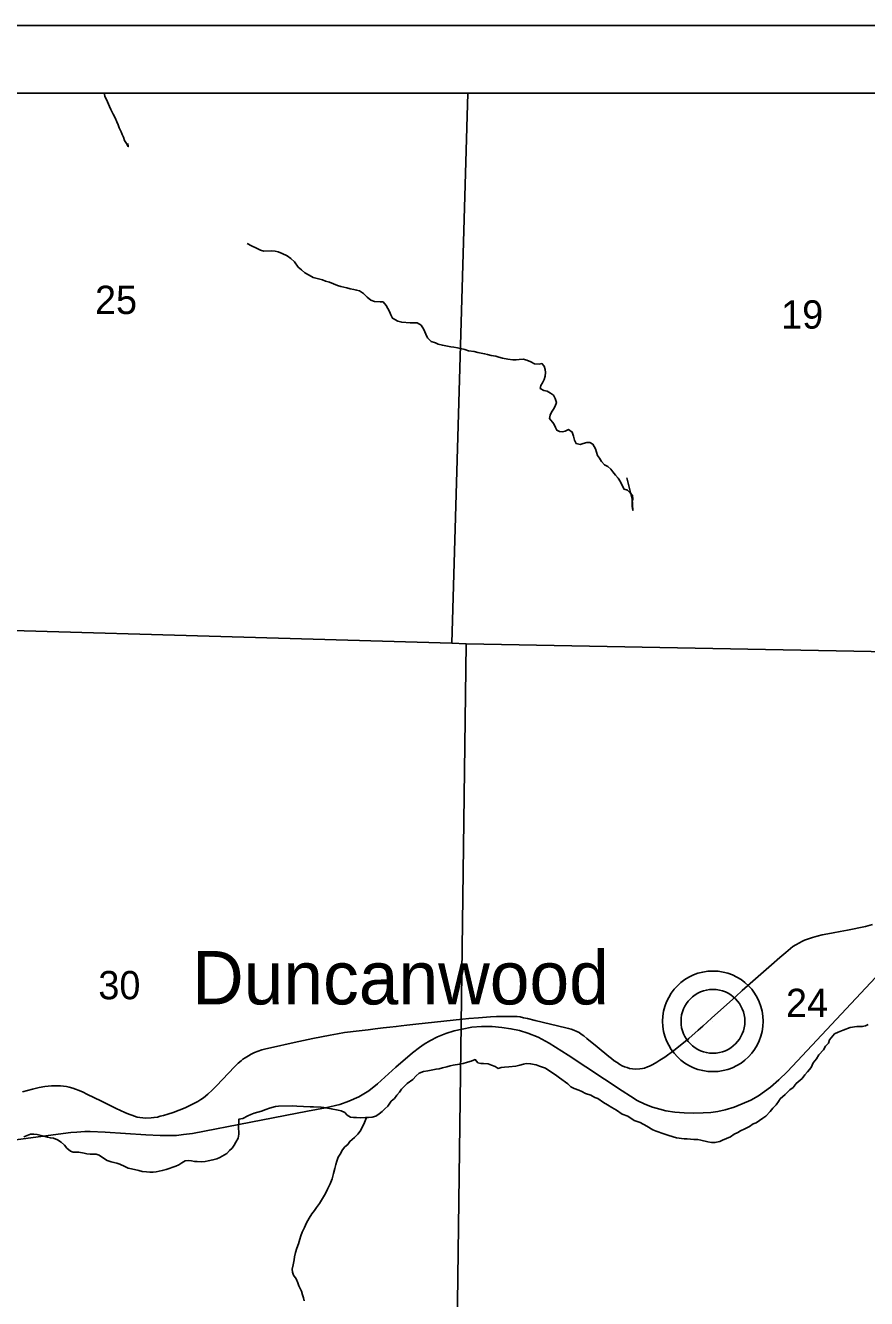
# Model space of a CAD drawing. Extents: x 0 to 34, y 0 to 22.
# Drawn here: x 6.653 to 7.897, y 18.617 to 20.5 of the extents above; entities that cross this region are included whole.
import ezdxf

# ---------------------------------------------------------------- set-up
doc = ezdxf.new("R2010")
doc.units = 0
for name, color, linetype in [('GM_X_Corporation', 7, 'Continuous'), ('GM_X_County_Road', 7, 'Continuous'), ('GM_X_Minor_River', 7, 'Continuous'), ('GM_X_Rail_Line', 7, 'Continuous'), ('GM_X_Section_Text', 7, 'Continuous'), ('GM_X_Unincorporated', 7, 'Continuous'), ('GM_X_Unincorporated_Location', 7, 'Continuous'), ('GM_X_Unincorporated_Text', 7, 'Continuous'), ('SH_Data', 7, 'Continuous')]:
    doc.layers.add(name, color=color, linetype=linetype)

msp = doc.modelspace()

# ---------------------------------------------------------------- linework, layer by layer
at = {"layer": 'GM_X_Corporation'}
for points in [[(9.4, 16.4853), (9.4, 20.4), (2.6, 20.4), (2.6, 16.6918), (3.1555, 16.6686), (3.1684, 16.6682), (4.0515, 16.6368), (4.1011, 16.6362), (4.1867, 16.6352), (4.5473, 16.6256), (4.6351, 16.6229), (5.4202, 16.5982), (6.0834, 16.5816), (6.2194, 16.578), (8.0963, 16.5226), (9.09, 16.4927)], [(9.4, 16.4853), (9.4, 20.4), (6.2895, 20.4), (6.2595, 19.6124), (6.2942, 19.6131), (6.2926, 19.1539), (6.292, 18.5898), (6.2786, 18.5898), (6.2744, 18.4654), (6.2729, 18.2077), (6.2194, 16.578), (8.0963, 16.5226), (9.09, 16.4927)], [(7.307, 20.4), (6.2866, 20.4), (6.258, 19.6163), (6.2913, 19.615), (7.2834, 19.5867)], [(8.3146, 20.4), (7.307, 20.4), (7.2834, 19.5867), (7.3046, 19.5855), (8.2946, 19.5667)], [(6.2913, 19.615), (7.2834, 19.5867), (7.3046, 19.5855), (7.291, 18.5737), (6.2882, 18.592)], [(8.2946, 19.5667), (8.3101, 19.5662), (8.2986, 18.5464), (7.291, 18.5737), (7.3046, 19.5855)]]:
    msp.add_lwpolyline(points, close=True, dxfattribs=at)
at = {"layer": 'GM_X_County_Road'}
msp.add_lwpolyline([(6.6483, 18.923), (6.6631, 18.9273), (6.673, 18.9296), (6.6814, 18.931), (6.6863, 18.9315), (6.6913, 18.9318), (6.696, 18.932), (6.7045, 18.9319), (6.7087, 18.9316), (6.7131, 18.931), (6.7173, 18.9301), (6.7225, 18.9287), (6.7268, 18.9273), (6.7322, 18.9252), (6.7378, 18.9226), (6.7436, 18.9199), (6.7652, 18.9093), (6.7866, 18.8987), (6.7931, 18.8955), (6.7997, 18.8925), (6.8054, 18.8901), (6.8099, 18.8885), (6.8138, 18.887), (6.818, 18.8859), (6.8219, 18.8851), (6.8261, 18.8846), (6.8305, 18.8844), (6.8387, 18.8846), (6.8426, 18.885), (6.8477, 18.8859), (6.8519, 18.887), (6.8568, 18.8883), (6.8631, 18.8902), (6.8711, 18.8928), (6.88, 18.8961), (6.8888, 18.8997), (6.8969, 18.9033), (6.9038, 18.9067), (6.9075, 18.9088), (6.9119, 18.9116), (6.9159, 18.9145), (6.9223, 18.9197), (6.929, 18.9258), (6.9353, 18.932), (6.9443, 18.9413), (6.9618, 18.9599), (6.9674, 18.9655), (6.9715, 18.9691), (6.9743, 18.9713), (6.9775, 18.9736), (6.9824, 18.9765), (6.9867, 18.9789), (6.9913, 18.9812), (6.9968, 18.9833), (7.0024, 18.9851), (7.0081, 18.9867), (7.0151, 18.9883), (7.0501, 18.9959), (7.0778, 19.0019), (7.1033, 19.0069), (7.1143, 19.009), (7.1246, 19.0108), (7.146, 19.0135), (7.1593, 19.0149), (7.1701, 19.0161), (7.1819, 19.0176), (7.1917, 19.0188), (7.2011, 19.0199), (7.2082, 19.0207), (7.2167, 19.0217), (7.2299, 19.0231), (7.2991, 19.0305), (7.3084, 19.0314), (7.3227, 19.0325), (7.3407, 19.0338), (7.3496, 19.0343), (7.3605, 19.0346), (7.3797, 19.0343), (7.3842, 19.0338), (7.3892, 19.0328), (7.3951, 19.0315), (7.4065, 19.0288), (7.4518, 19.0179), (7.456, 19.0168), (7.46, 19.0156), (7.464, 19.0143), (7.468, 19.0126), (7.4714, 19.0107), (7.4748, 19.0086), (7.4786, 19.0057), (7.4831, 19.0022), (7.4982, 18.9898), (7.5155, 18.9753), (7.5194, 18.9722), (7.5235, 18.9691), (7.5278, 18.9663), (7.5317, 18.9636), (7.5353, 18.9617), (7.5388, 18.9603), (7.5428, 18.9589), (7.5463, 18.9578), (7.5506, 18.9571), (7.5543, 18.9567), (7.5614, 18.957), (7.5653, 18.9576), (7.5681, 18.9583), (7.5726, 18.9599), (7.5758, 18.9612), (7.5804, 18.9635), (7.5867, 18.967), (7.5911, 18.9698), (7.5983, 18.9745), (7.6118, 18.9844), (7.6237, 18.9936), (7.6341, 19.0022), (7.6475, 19.0141), (7.6545, 19.0203), (7.6673, 19.0322), (7.7035, 19.0643), (7.713, 19.0731), (7.7561, 19.1111), (7.7685, 19.1218), (7.7773, 19.1293), (7.7843, 19.1353), (7.7878, 19.1378), (7.7921, 19.1405), (7.7974, 19.1436), (7.8011, 19.1455), (7.8052, 19.1474), (7.8108, 19.1495), (7.8166, 19.1514), (7.8237, 19.1533), (7.8312, 19.1551), (7.8393, 19.1567), (7.8475, 19.1584), (7.8579, 19.1603), (7.8684, 19.1624), (7.8951, 19.1678), (7.9054, 19.1707)], dxfattribs=at)
at = {"layer": 'GM_X_Minor_River'}
for points in [[(6.7689, 20.4), (6.7701, 20.3955), (6.7742, 20.3873), (6.7768, 20.3802), (6.7788, 20.3757), (6.7821, 20.369), (6.7853, 20.3634), (6.7878, 20.3574), (6.7899, 20.3533), (6.7912, 20.3488), (6.7941, 20.3428), (6.7957, 20.3387), (6.7978, 20.3346), (6.7991, 20.3301), (6.8019, 20.3257), (6.8047, 20.3208), (6.8038, 20.3257)], [(6.9804, 20.1775), (6.9869, 20.1743), (6.9946, 20.1708), (7.0005, 20.1676), (7.0054, 20.1662), (7.0161, 20.1666), (7.0218, 20.166), (7.0264, 20.1651), (7.0325, 20.1626), (7.0395, 20.1594), (7.0449, 20.1555), (7.0504, 20.1503), (7.056, 20.1426), (7.0607, 20.1386), (7.0658, 20.1342), (7.0724, 20.131), (7.0782, 20.1274), (7.092, 20.1237), (7.0966, 20.122), (7.1024, 20.1203), (7.114, 20.1154), (7.1193, 20.1141), (7.1278, 20.1121), (7.1331, 20.1107), (7.1381, 20.1098), (7.1423, 20.1088), (7.1465, 20.1074), (7.1524, 20.1035), (7.1583, 20.098), (7.1634, 20.0936), (7.1691, 20.0919), (7.1771, 20.0914), (7.1817, 20.0912), (7.1861, 20.0857), (7.1913, 20.0768), (7.193, 20.0719), (7.1955, 20.067), (7.2032, 20.0628), (7.2093, 20.0611), (7.2219, 20.0604), (7.2261, 20.0605), (7.2322, 20.0604), (7.238, 20.0568), (7.242, 20.0505), (7.2449, 20.0434), (7.2474, 20.0381), (7.2525, 20.0326), (7.259, 20.0306), (7.2633, 20.0288), (7.2694, 20.0272), (7.282, 20.0249), (7.2862, 20.0243), (7.2916, 20.0234), (7.3023, 20.0207), (7.3081, 20.019), (7.3161, 20.0178), (7.3218, 20.0165), (7.3318, 20.0145), (7.336, 20.0136), (7.3417, 20.0122), (7.3486, 20.011), (7.3528, 20.0096), (7.3582, 20.0079), (7.3662, 20.0063), (7.3735, 20.0058), (7.3784, 20.0055), (7.383, 20.0061), (7.3886, 20.0063), (7.394, 20.0049), (7.4002, 20.0025), (7.4056, 19.9997), (7.4124, 19.9991), (7.4166, 20), (7.4198, 19.996), (7.4215, 19.9915), (7.4216, 19.9866), (7.4214, 19.9813), (7.4197, 19.9763), (7.4172, 19.9717), (7.4151, 19.9674), (7.4141, 19.9632), (7.4192, 19.96), (7.4245, 19.959), (7.4292, 19.9565), (7.4338, 19.9533), (7.4363, 19.9485), (7.438, 19.9425), (7.4363, 19.9371), (7.4338, 19.9328), (7.4309, 19.9282), (7.4288, 19.9236), (7.4279, 19.919), (7.4342, 19.9109), (7.4367, 19.9057), (7.4384, 19.9016), (7.4426, 19.8998), (7.4468, 19.8992), (7.4509, 19.9001), (7.4558, 19.9025), (7.4613, 19.8986), (7.4634, 19.8926)], [(7.4634, 19.8926), (7.4647, 19.8869), (7.4672, 19.8817), (7.4729, 19.8804), (7.4778, 19.8817), (7.4831, 19.8834), (7.4876, 19.8832), (7.4919, 19.8807), (7.4959, 19.874), (7.4973, 19.8688), (7.4989, 19.8643), (7.5017, 19.8602), (7.5046, 19.855), (7.5089, 19.8502), (7.514, 19.8477), (7.5183, 19.8441), (7.5215, 19.8401), (7.5254, 19.8349), (7.5294, 19.8305), (7.5326, 19.8253), (7.5351, 19.8197), (7.538, 19.8145), (7.5429, 19.8128), (7.5473, 19.8091), (7.5505, 19.8047), (7.551, 19.7994), (7.55, 19.7949), (7.5499, 19.7892), (7.5512, 19.7828), (7.5499, 19.7994), (7.5423, 19.8309)], [(7.8993, 19.0226), (7.8952, 19.0206), (7.8903, 19.0196), (7.8823, 19.0197), (7.8725, 19.0183), (7.862, 19.0145), (7.8549, 19.0116), (7.8493, 19.0088), (7.842, 18.9999), (7.8403, 18.9953), (7.8359, 18.9906), (7.833, 18.9852), (7.8261, 18.9778), (7.8229, 18.9717), (7.8178, 18.9658), (7.815, 18.9593), (7.8092, 18.9527), (7.8055, 18.9481), (7.8015, 18.943), (7.7927, 18.9355)], [(7.7927, 18.9355), (7.788, 18.9297), (7.7835, 18.9262), (7.7762, 18.9191), (7.7692, 18.9129), (7.7663, 18.9086), (7.7631, 18.904), (7.758, 18.8989), (7.7543, 18.8939), (7.7478, 18.8872), (7.7433, 18.8841), (7.7337, 18.8773), (7.7292, 18.8757), (7.7236, 18.8721), (7.7169, 18.8685), (7.7102, 18.8656), (7.7061, 18.8632), (7.7009, 18.8604), (7.6953, 18.8564), (7.6897, 18.8543), (7.6837, 18.8515), (7.6796, 18.8498), (7.6725, 18.8481), (7.6675, 18.8483), (7.6622, 18.8492), (7.6518, 18.8515), (7.6473, 18.8525), (7.6412, 18.8526), (7.6313, 18.8534), (7.6271, 18.8537), (7.6156, 18.8552), (7.6041, 18.8585), (7.5968, 18.8609), (7.5853, 18.865), (7.5807, 18.8671), (7.5717, 18.8725), (7.5617, 18.8778), (7.5528, 18.8809), (7.5435, 18.8874), (7.5354, 18.8901), (7.5268, 18.8958), (7.5198, 18.9001), (7.5136, 18.9037), (7.5078, 18.9076), (7.4992, 18.9134), (7.495, 18.9147), (7.4888, 18.9183), (7.4811, 18.9206), (7.4757, 18.9235), (7.4711, 18.9256), (7.4641, 18.928), (7.4595, 18.9305), (7.4551, 18.9348), (7.4427, 18.9438), (7.4364, 18.9481), (7.4314, 18.9517), (7.422, 18.9582), (7.4132, 18.9613), (7.4078, 18.963), (7.3998, 18.9646), (7.3933, 18.9648), (7.3892, 18.9639), (7.3839, 18.9625), (7.3782, 18.9612), (7.3676, 18.9601), (7.3612, 18.9595), (7.3563, 18.9589), (7.3518, 18.9577), (7.3475, 18.9605), (7.3421, 18.9626), (7.3371, 18.9643), (7.3303, 18.9648), (7.3261, 18.9651), (7.3219, 18.966), (7.3179, 18.9708), (7.3119, 18.9687), (7.3066, 18.967), (7.2999, 18.9649), (7.2946, 18.964), (7.2852, 18.9625), (7.2806, 18.9616), (7.2761, 18.9599), (7.2694, 18.9586), (7.2645, 18.9573), (7.2599, 18.9567), (7.2554, 18.9558), (7.2479, 18.9544), (7.2415, 18.9531), (7.2351, 18.9506), (7.2307, 18.947), (7.2256, 18.9412), (7.2174, 18.9353), (7.213, 18.931), (7.2086, 18.927), (7.2057, 18.9228), (7.2017, 18.9181), (7.1985, 18.9135), (7.1937, 18.9092), (7.1886, 18.9018), (7.1842, 18.8979), (7.1802, 18.894)], [(7.1802, 18.894), (7.1758, 18.8908), (7.1709, 18.8873), (7.1653, 18.8856), (7.16, 18.885), (7.1558, 18.8852), (7.1475, 18.8849), (7.1425, 18.8852), (7.138, 18.885), (7.1334, 18.8856), (7.1287, 18.8884), (7.1248, 18.8928), (7.1198, 18.8949), (7.1152, 18.8959), (7.1049, 18.8982), (7.0938, 18.9), (7.0896, 18.9007), (7.0785, 18.901), (7.0736, 18.9012), (7.0542, 18.9021), (7.0481, 18.9026), (7.0269, 18.9019), (7.0227, 18.9013), (7.0137, 18.8991), (7.0084, 18.8971), (7.0017, 18.8946), (6.9961, 18.8929), (6.9908, 18.8916), (6.9859, 18.8895), (6.9814, 18.8875), (6.974, 18.8838), (6.968, 18.8825), (6.9681, 18.8776), (6.9679, 18.8723), (6.9684, 18.8603), (6.9671, 18.8546), (6.9639, 18.8488), (6.9614, 18.8442), (6.9585, 18.8399), (6.9545, 18.8364), (6.9504, 18.8321), (6.94, 18.8261), (6.9359, 18.8241), (6.9299, 18.8224), (6.9227, 18.821), (6.9182, 18.8201), (6.9125, 18.8195), (6.9068, 18.82), (6.9026, 18.8203), (6.8981, 18.8209), (6.8931, 18.8215), (6.8889, 18.8213), (6.8837, 18.8181), (6.8793, 18.8153), (6.8748, 18.8133), (6.8707, 18.8116), (6.8651, 18.8096), (6.8609, 18.8083), (6.8549, 18.8066), (6.8459, 18.8047), (6.8413, 18.8042), (6.8368, 18.8044), (6.8314, 18.8046), (6.8253, 18.8055), (6.8203, 18.8069), (6.8096, 18.8091), (6.8043, 18.8105), (6.7996, 18.8129), (6.7923, 18.8164), (6.7877, 18.8178), (6.7835, 18.8188), (6.7793, 18.8194), (6.7735, 18.8214), (6.7665, 18.8261), (6.7618, 18.8297), (6.7572, 18.8311), (6.7526, 18.8309), (6.7484, 18.8311), (6.7435, 18.8313), (6.7393, 18.8323), (6.7316, 18.8339), (6.7275, 18.8338), (6.7233, 18.834), (6.719, 18.8354), (6.714, 18.8397), (6.7104, 18.8441), (6.7053, 18.8488), (6.6998, 18.8521), (6.694, 18.8545), (6.6895, 18.8551), (6.6853, 18.8561), (6.6799, 18.8574), (6.6699, 18.8601), (6.665, 18.8606), (6.66, 18.8605), (6.6552, 18.8588), (6.6503, 18.8567)], [(7.1571, 18.8852), (7.1542, 18.8776), (7.1517, 18.8723), (7.1478, 18.865), (7.1442, 18.8607), (7.1394, 18.8556), (7.1324, 18.8497), (7.1296, 18.8455), (7.1251, 18.8416), (7.1215, 18.8373), (7.1179, 18.8311), (7.1154, 18.8265), (7.113, 18.8204), (7.1117, 18.8155), (7.1104, 18.8098), (7.1083, 18.8025), (7.1064, 18.7946), (7.1032, 18.7873), (7.0993, 18.7792), (7.0965, 18.7727), (7.0922, 18.7654), (7.0876, 18.7581), (7.0832, 18.7519), (7.0803, 18.7477), (7.0764, 18.7427), (7.0724, 18.7365), (7.0685, 18.7292), (7.0653, 18.7227), (7.0621, 18.7158), (7.0601, 18.7101), (7.0583, 18.7055), (7.0563, 18.6986), (7.0539, 18.6918), (7.0522, 18.6857), (7.0506, 18.6792), (7.05, 18.6747), (7.0484, 18.6671), (7.0471, 18.6607), (7.0476, 18.6565), (7.0493, 18.6521), (7.0529, 18.6466), (7.0554, 18.6406), (7.0571, 18.6362), (7.0608, 18.6284), (7.0625, 18.6228), (7.0638, 18.6187), (7.0651, 18.6142)]]:
    msp.add_lwpolyline(points, dxfattribs=at)
at = {"layer": 'GM_X_Rail_Line'}
msp.add_lwpolyline([(7.9317, 19.1156), (7.7798, 18.9531), (7.7672, 18.9407), (7.7548, 18.9299), (7.737, 18.9172), (7.7258, 18.9109), (7.713, 18.9053), (7.7008, 18.9007), (7.6876, 18.8967), (7.677, 18.8941), (7.6663, 18.8928), (7.6551, 18.8921), (7.641, 18.8916), (7.627, 18.8919), (7.6134, 18.8931), (7.5998, 18.8952), (7.5909, 18.8973), (7.58, 18.9004), (7.5689, 18.905), (7.5575, 18.9105), (7.5476, 18.9168), (7.5353, 18.9248), (7.4553, 18.9772), (7.4273, 18.9951), (7.4108, 19.0038), (7.3956, 19.0097), (7.3836, 19.0136), (7.3706, 19.0164), (7.3572, 19.0184), (7.3429, 19.0199), (7.3271, 19.0197), (7.313, 19.0186), (7.2988, 19.0159), (7.2869, 19.0131), (7.2745, 19.0093), (7.2622, 19.0043), (7.2509, 18.9986), (7.2426, 18.9937), (7.2354, 18.9889), (7.2249, 18.981), (7.2005, 18.9595), (7.1734, 18.9349), (7.1603, 18.9248), (7.1459, 18.9156), (7.1308, 18.9092), (7.1177, 18.9046), (7.0962, 18.8994), (7.0699, 18.8945), (6.9862, 18.8783), (6.8999, 18.8617), (6.8862, 18.8598), (6.8759, 18.8588), (6.8627, 18.8585), (6.8519, 18.8587), (6.8307, 18.8597), (6.7705, 18.8635), (6.7483, 18.8643), (6.7405, 18.8645), (6.7285, 18.8636), (6.7197, 18.8628), (6.4854, 18.8319)], dxfattribs=at)
at = {"layer": 'GM_X_Unincorporated'}
for radius in [0.0744, 0.0472]:
    msp.add_circle((7.6695, 19.0274), radius, dxfattribs=at)
at = {"layer": 'GM_X_Unincorporated_Location'}
msp.add_line((7.6695, 19.0274), (7.6695, 19.0274), dxfattribs=at)
at = {"layer": 'SH_Data'}
for points in [[(2.5, 20.5), (9.5, 20.5), (9.5, 13.5), (2.5, 13.5)], [(2.6, 20.4), (9.4, 20.4), (9.4, 13.6), (2.6, 13.6)]]:
    msp.add_lwpolyline(points, close=True, dxfattribs=at)

# ---------------------------------------------------------------- texts
at = {"layer": 'GM_X_Section_Text'}
for s, p in [('25', (6.7554, 20.0733)), ('19', (7.7704, 20.0517)), ('30', (6.7604, 19.06)), ('24', (7.7775, 19.0337))]:
    msp.add_text(s, height=0.04186, rotation=0, dxfattribs=at).set_placement(p)
at = {"layer": 'GM_X_Unincorporated_Text'}
msp.add_text('Duncanwood', height=0.07898, rotation=0, dxfattribs=at).set_placement((6.8991, 19.0524))

doc.saveas('drawing.dxf')
